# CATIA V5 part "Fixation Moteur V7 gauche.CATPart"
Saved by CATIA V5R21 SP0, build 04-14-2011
Part number: MOTEURGAUCHE
Bounding box of the stored display mesh (mm): x -4.2 to 4.2, y -40 to 0, z -20 to 40
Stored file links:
  C:\Users\2027.DESARCY-LEMIE30\Desktop\V16(05.04.2023)\Fixation Moteur V7 gauche.CATPart
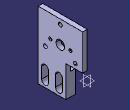
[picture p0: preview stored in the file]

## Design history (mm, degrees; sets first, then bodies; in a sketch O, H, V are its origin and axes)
Body1 (main body)
  Sketch1 on yz-plane, origin (0, 0, 0), H (0, 1, 0), V (0, 0, 1)
    line L1 (-40, 40) -> (0, 40)
    line L2 (0, 40) -> (0, 0)
    line L3 (0, 0) -> (-40, 0)
    line L4 (-40, 0) -> (-40, 40)
    point P3 (0, 0)
    length L4 = 40
    length L1 = 40
    horizontal: L1 H, L3 H
    vertical: L2 V, L4 V
    coincidence: P3 O
  Pad1: profile Sketch1, direction (1, 0, 0), length 4.2
  Sketch2 on end face of Pad1, origin (4.2, 0, 0), H (0, 1, 0), V (0, 0, 1)
    point P1 (-40, 0)
    line L1 (-40, 0) -> (-15, 0)
    line L2 (-15, 0) -> (-15, -20)
    line L3 (-15, -20) -> (-40, -20)
    line L4 (-40, -20) -> (-40, 0)
    reference projected point E1 (-40, 0) from vertex [face of Pad1 from Sketch1.L3 | end face of Pad1 | face of Pad1 from Sketch1.L4]
    length L2 = 20
    length L3 = 25
    horizontal: L1 H, L3 H
    vertical: L2 V, L4 V
    coincidence: P1 E1
  Pad2: profile Sketch2, direction (-1, 0, 0), length 8.4
  Sketch3 on end face of Pad2, origin (-4.2, 0, 0), H (0, -1, 0), V (0, 0, 1)
    point P1 (18.15, -5)
    line L1 (24.35, -5) -> (24.35, -15)
    line L2 (18.15, -15) -> (18.15, -5)
    point P2 (24.35, -5)
    point P3 (24.35, -15)
    point P4 (18.15, -15)
    axis line L3 (27.5, 2.3624) -> (27.5, -21.6714)
    reference projected line E1 (40, 0) -> (40, -20) from edge [end face of Pad2 | face of Pad2 from Sketch2.L4]
    arc A1 centre (21.25, -5) radius 3.1 from (24.35, -5) to (18.15, -5) ccw
    point P8 (10.7649, -15.4491)
    arc A2 centre (21.25, -15) radius 3.1 from (18.15, -15) to (24.35, -15) ccw
    point P9 (21.25, -15)
    point P10 (18.15, -15)
    point P11 (24.35, -15)
    point P12 (36.85, -5)
    point P13 (36.85, -15)
    line L4 (36.85, -15) -> (36.85, -5)
    point P14 (30.65, -5)
    arc A3 centre (33.75, -5) radius 3.1 from (30.65, -5) to (36.85, -5) cw
    point P16 (30.65, -15)
    line L5 (30.65, -5) -> (30.65, -15)
    point P17 (30.65, -15)
    point P18 (36.85, -15)
    point P19 (33.75, -15)
    arc A4 centre (33.75, -15) radius 3.1 from (36.85, -15) to (30.65, -15) cw
    reference projected line E2 (40, -20) -> (15, -20) from edge [end face of Pad2 | face of Pad2 from Sketch2.L3]
    distance L3 E1 = 12.5
    radius A1 = 3.1
    distance P9 P19 = 12.5
    length L4 = 10
    distance A4 E2 = 1.9
    vertical: L1 V, L2 V, L3 V
    tangency: A1 L1, A1 L2, A2 L1, A2 L2
    coincidence: P4 A2, L1 P11, L2 P10, P3 P11, P4 P10, P13 P18, P16 P17
    symmetry: P1 P12 L3, P4 P13 L3, L2 L4 L3, P2 P14 L3, A1 A3 L3, P3 P16 L3, L1 L5 L3, P11 P17 L3, P10 P18 L3, A2 A4 L3
  Pocket1: profile Sketch3, direction (1, 0, 0), through (limit type 3)
  Sketch4 on start face of Pad1, origin (0, 0, 0), H (0, -1, 0), V (0, 0, 1)
    construction line L1 (0, 20) -> (40, 20)
    point P1 (0, 20)
    point P2 (40, 20)
    reference projected line E1 (0, 40) -> (40, 40) from edge [start face of Pad1 | face of Pad1 from Sketch1.L1]
    reference projected line E2 (0, 0) -> (0, 40) from edge [start face of Pad1 | face of Pad2]
    reference projected line E3 (40, 40) -> (40, 0) from edge [start face of Pad1 | face of Pad1 from Sketch1.L4]
    construction line L2 (20, 40) -> (20, 0)
    point P3 (20, 40)
    point P4 (20, 0)
    reference projected line E4 (0, 40) -> (40, 40) from edge [start face of Pad1 | face of Pad1 from Sketch1.L1]
    reference projected line E5 (40, 0) -> (0, 0) from edge [start face of Pad1 | face of Pad1 from Sketch1.L3]
    reference projected line E6 (40, 40) -> (40, 0) from edge [start face of Pad1 | face of Pad1 from Sketch1.L4]
    circle A1 centre (20, 20) radius 4
    point P5 (20, 20)
    construction line L3 (20, 20) -> (0, 8.453)
    point P6 (0, 8.453)
    axis line L4 (20, 20) -> (40, 8.453)
    point P7 (40, 8.453)
    reference projected line E7 (40, 40) -> (40, 0) from edge [start face of Pad1 | face of Pad1 from Sketch1.L4]
    circle A2 centre (20, 35.5885) radius 1.75
    point P8 (20, 35.5885)
    point P9 (33.5, 12.2058)
    circle A3 centre (33.5, 12.2058) radius 1.75
    point P10 (6.5, 12.2058)
    circle A4 centre (6.5, 12.2058) radius 1.75
    distance E1 L1 = 20
    distance L2 E6 = 20
    radius A1 = 4
    angle L3 L2 = 120
    angle L2 L4 = 120
    radius A2 = 1.75
    distance P9 P10 = 27
    horizontal: L1 H
    coincidence: P1 E2, P2 E3, E4 P3, P4 E5, P5 L2, P6 V, P7 E7, P8 L2
    vertical: L2 V
    midpoint: P5 L2
    symmetry: A2 A3 L3, A3 A4 L2
  Pocket2: profile Sketch4, direction (1, 0, 0), through (limit type 3)
  Sketch5 on start face of Pad1, origin (0, -33.6663, 26.8229), H (0, 1, 0), V (0, 0, -1)
    point P1 (22.6663, 6.8229)
    axis line L1 (13.6663, 6.8229) -> (56.6573, 6.8229)
    point P2 (13.6663, 6.8229)
    reference projected circle E1 centre (13.6663, 6.8229) radius 4 from edge [start face of Pad1 | face of Pocket2 from Sketch4.A1]
    distance P2 P1 = 9
    horizontal: L1 H
    concentricity: P2 E1
    coincidence: P1 L1
  Hole1: placed by Sketch5, at (0, -11, 20) direction (1, 0, 0), diameter 3, through (limit type 6), counterbore diameter 6, counterbore depth 3
  RectPattern1: of Hole1, direction 1 instances 2, spacing 18, along face of Pad1 from Sketch1.L1 reversed
  Sketch6 on start face of Pad1, origin (0, 0, 0), H (0, -1, 0), V (0, 0, 1)
    line L1 (0, 0) -> (15, 0)
    line L2 (15, 0) -> (15, 8)
    line L3 (15, 8) -> (0, 8)
    line L4 (0, 8) -> (0, 0)
    reference projected line E1 (15, -20) -> (15, 0) from edge [end face of Pad2 | face of Pad2 from Sketch2.L2]
    length L2 = 8
    horizontal: L1 H, L3 H
    vertical: L2 V, L4 V
    coincidence: L2 E1
  Pocket3: profile Sketch6, direction (1, 0, 0), through (limit type 3)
